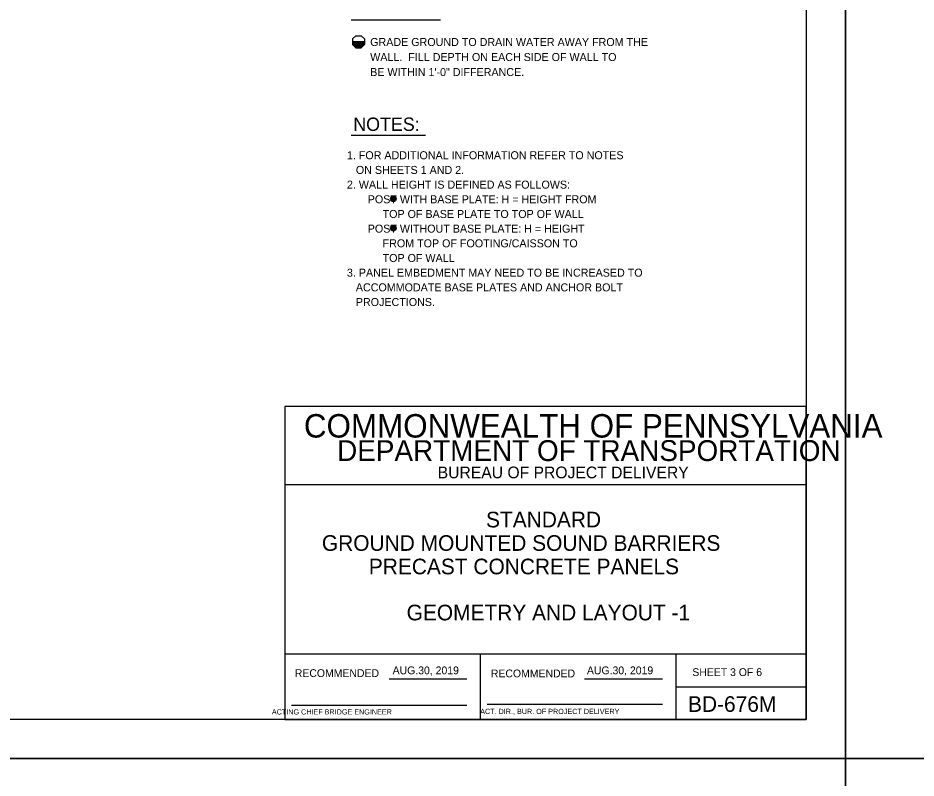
# Model space of a CAD drawing. Extents: x 3761 to 5458, y -616 to 1166.
# Drawn here: x 4284.9 to 4629.5, y -29.8 to 261.8 of the extents above; entities that cross this region are included whole.
import ezdxf

# ---------------------------------------------------------------- set-up
doc = ezdxf.new("R2010")
doc.units = 0
for name, color, linetype in [('1', 7, 'Continuous'), ('2', 7, 'Continuous'), ('PLT-BNDY', 7, 'Continuous')]:
    doc.layers.add(name, color=color, linetype=linetype)

msp = doc.modelspace()

# ---------------------------------------------------------------- linework, layer by layer
at = {"layer": '1'}
for p, q in [((4412.72, 261.03), (4447.03, 261.03)), ((4414.49, 255.01), (4413.23, 253.76)), ((4414.49, 255.01), (4416.6, 255.01)), ((4416.6, 255.01), (4417.85, 253.76)), ((4413.22, 252.82), (4417.84, 252.82)), ((4413.22, 251.72), (4417.84, 251.72)), ((4413.23, 253.76), (4413.23, 251.64)), ((4413.23, 252.12), (4417.84, 252.12)), ((4413.23, 252.02), (4417.84, 252.02)), ((4413.23, 251.92), (4417.84, 251.92)), ((4413.23, 251.82), (4417.84, 251.82)), ((4414.49, 250.39), (4413.23, 251.64)), ((4413.24, 252.62), (4417.84, 252.62)), ((4413.24, 252.52), (4417.84, 252.52)), ((4413.24, 252.42), (4417.84, 252.42)), ((4413.24, 252.32), (4417.84, 252.32)), ((4413.24, 252.22), (4417.84, 252.22)), ((4413.24, 251.62), (4417.8, 251.62)), ((4413.25, 252.72), (4417.84, 252.72)), ((4416.33, 252.82), (4417.84, 252.82)), ((4416.6, 250.39), (4417.85, 251.64)), ((4417.85, 253.76), (4417.85, 251.64)), ((4413.35, 251.52), (4417.7, 251.52)), ((4413.45, 251.42), (4417.61, 251.42)), ((4413.55, 251.32), (4417.51, 251.32)), ((4413.65, 251.22), (4417.41, 251.22)), ((4413.75, 251.12), (4417.32, 251.12)), ((4413.86, 251.02), (4417.22, 251.02)), ((4413.96, 250.92), (4417.13, 250.92)), ((4414.06, 250.82), (4417.03, 250.82)), ((4414.16, 250.72), (4416.93, 250.72)), ((4414.26, 250.62), (4416.84, 250.62)), ((4414.36, 250.52), (4416.74, 250.52)), ((4414.47, 250.42), (4416.65, 250.42)), ((4414.49, 250.39), (4416.6, 250.39)), ((4412.71, 216.85), (4441.28, 216.85))]:
    msp.add_line(p, q, dxfattribs=at)
for centre, radius in [((4428.92, 192.41), 1.07), ((4428.92, 192.41), 0.8), ((4428.92, 192.41), 0.533), ((4428.92, 192.41), 0.267), ((4428.92, 181.15), 1.07), ((4428.92, 181.15), 0.8), ((4428.92, 181.15), 0.533), ((4428.92, 181.15), 0.267)]:
    msp.add_circle(centre, radius, dxfattribs=at)
at = {"layer": '2'}
for p, q in [((4587.34, 556.69), (4587.34, -7.31)), ((4587.34, 112.69), (4387.34, 112.69)), ((4387.34, 112.69), (4387.34, -7.31)), ((4587.34, -7.31), (4587.34, 112.69)), ((4587.34, 82.69), (4387.34, 82.69)), ((4587.34, 17.69), (4387.34, 17.69)), ((4462.34, -7.31), (4462.34, 17.69)), ((4537.34, 17.69), (4537.34, -7.31)), ((4427.31, 8.19), (4457.07, 8.19)), ((4502.31, 8.19), (4532.21, 8.19)), ((4537.34, 5.19), (4587.34, 5.19)), ((4389.84, -1.81), (4457.07, -1.81)), ((4464.97, -1.43), (4532.21, -1.43)), ((4587.34, -7.31), (3801.34, -7.31)), ((4387.34, -7.31), (4587.34, -7.31))]:
    msp.add_line(p, q, dxfattribs=at)
at = {"layer": 'PLT-BNDY'}
for points in [[(3761.34, 571.69), (4602.34, 571.69), (4602.34, -22.31), (3761.34, -22.31)], [(4602.34, 571.69), (5443.34, 571.69), (5443.34, -22.31), (4602.34, -22.31)], [(3761.34, -22.31), (4602.34, -22.31), (4602.34, -616.31), (3761.34, -616.31)], [(4602.34, -22.31), (5443.34, -22.31), (5443.34, -616.31), (4602.34, -616.31)]]:
    msp.add_lwpolyline(points, close=True, dxfattribs=at)

# ---------------------------------------------------------------- texts
at = {"layer": '1'}
for s, height, p in [('GRADE GROUND TO DRAIN WATER AWAY FROM THE', 3.072, (4420.03, 251.04)), ('WALL.  FILL DEPTH ON EACH SIDE OF WALL TO', 3.072, (4420.03, 245.28)), ('BE WITHIN 1\'-0" DIFFERANCE.', 3.072, (4420.03, 239.52)), ('NOTES:', 5.117, (4413.54, 218.48)), ('1. FOR ADDITIONAL INFORMATION REFER TO NOTES ', 3.072, (4411.1, 207.6)), ('   ON SHEETS 1 AND 2.', 3.072, (4411.1, 201.97)), ('2. WALL HEIGHT IS DEFINED AS FOLLOWS:', 3.072, (4411.1, 196.33)), ('       POST WITH BASE PLATE: H = HEIGHT FROM', 3.072, (4411.1, 190.7)), ('            TOP OF BASE PLATE TO TOP OF WALL', 3.072, (4411.1, 185.07)), ('       POST WITHOUT BASE PLATE: H = HEIGHT', 3.072, (4411.1, 179.44)), ('            FROM TOP OF FOOTING/CAISSON TO', 3.072, (4411.1, 173.81)), ('            TOP OF WALL', 3.072, (4411.1, 168.18)), ('3. PANEL EMBEDMENT MAY NEED TO BE INCREASED TO', 3.072, (4411.1, 162.55)), ('   ACCOMMODATE BASE PLATES AND ANCHOR BOLT', 3.072, (4411.1, 156.91)), ('   PROJECTIONS.', 3.072, (4411.1, 151.28)), ('STANDARD', 6, (4464.48, 66.36)), ('GROUND MOUNTED SOUND BARRIERS', 6, (4401.5, 57.36)), ('PRECAST CONCRETE PANELS', 6, (4419.5, 48.36)), ('GEOMETRY AND LAYOUT -1', 6, (4434, 30.69)), ('SHEET 3 OF 6', 3, (4543.63, 9.32)), ('BD-676M', 6, (4541.97, -4.43))]:
    msp.add_text(s, height=height, dxfattribs=at).set_placement(p)
at = {"layer": '2'}
for s, height, p in [('COMMONWEALTH OF PENNSYLVANIA', 9, (4394.59, 100.82)), ('DEPARTMENT OF TRANSPORTATION', 8.0002, (4407.34, 91.82)), ('BUREAU OF PROJECT DELIVERY', 4.5, (4445.93, 85.19)), ('AUG.30, 2019', 3, (4428.64, 10)), ('AUG.30, 2019', 3, (4503.19, 10)), ('       ACTING CHIEF BRIDGE ENGINEER', 2.0002, (4376.93, -5.43)), ('  ACT. DIR., BUR. OF PROJECT DELIVERY', 2.0002, (4460.71, -5.25))]:
    msp.add_text(s, height=height, dxfattribs=at).set_placement(p)
for p in [(4391.11, 8.94), (4466.33, 8.82)]:
    msp.add_text('RECOMMENDED', height=3, rotation=360, dxfattribs=at).set_placement(p)

doc.saveas('drawing.dxf')
